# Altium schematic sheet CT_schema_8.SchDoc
size 371 x 336 mm
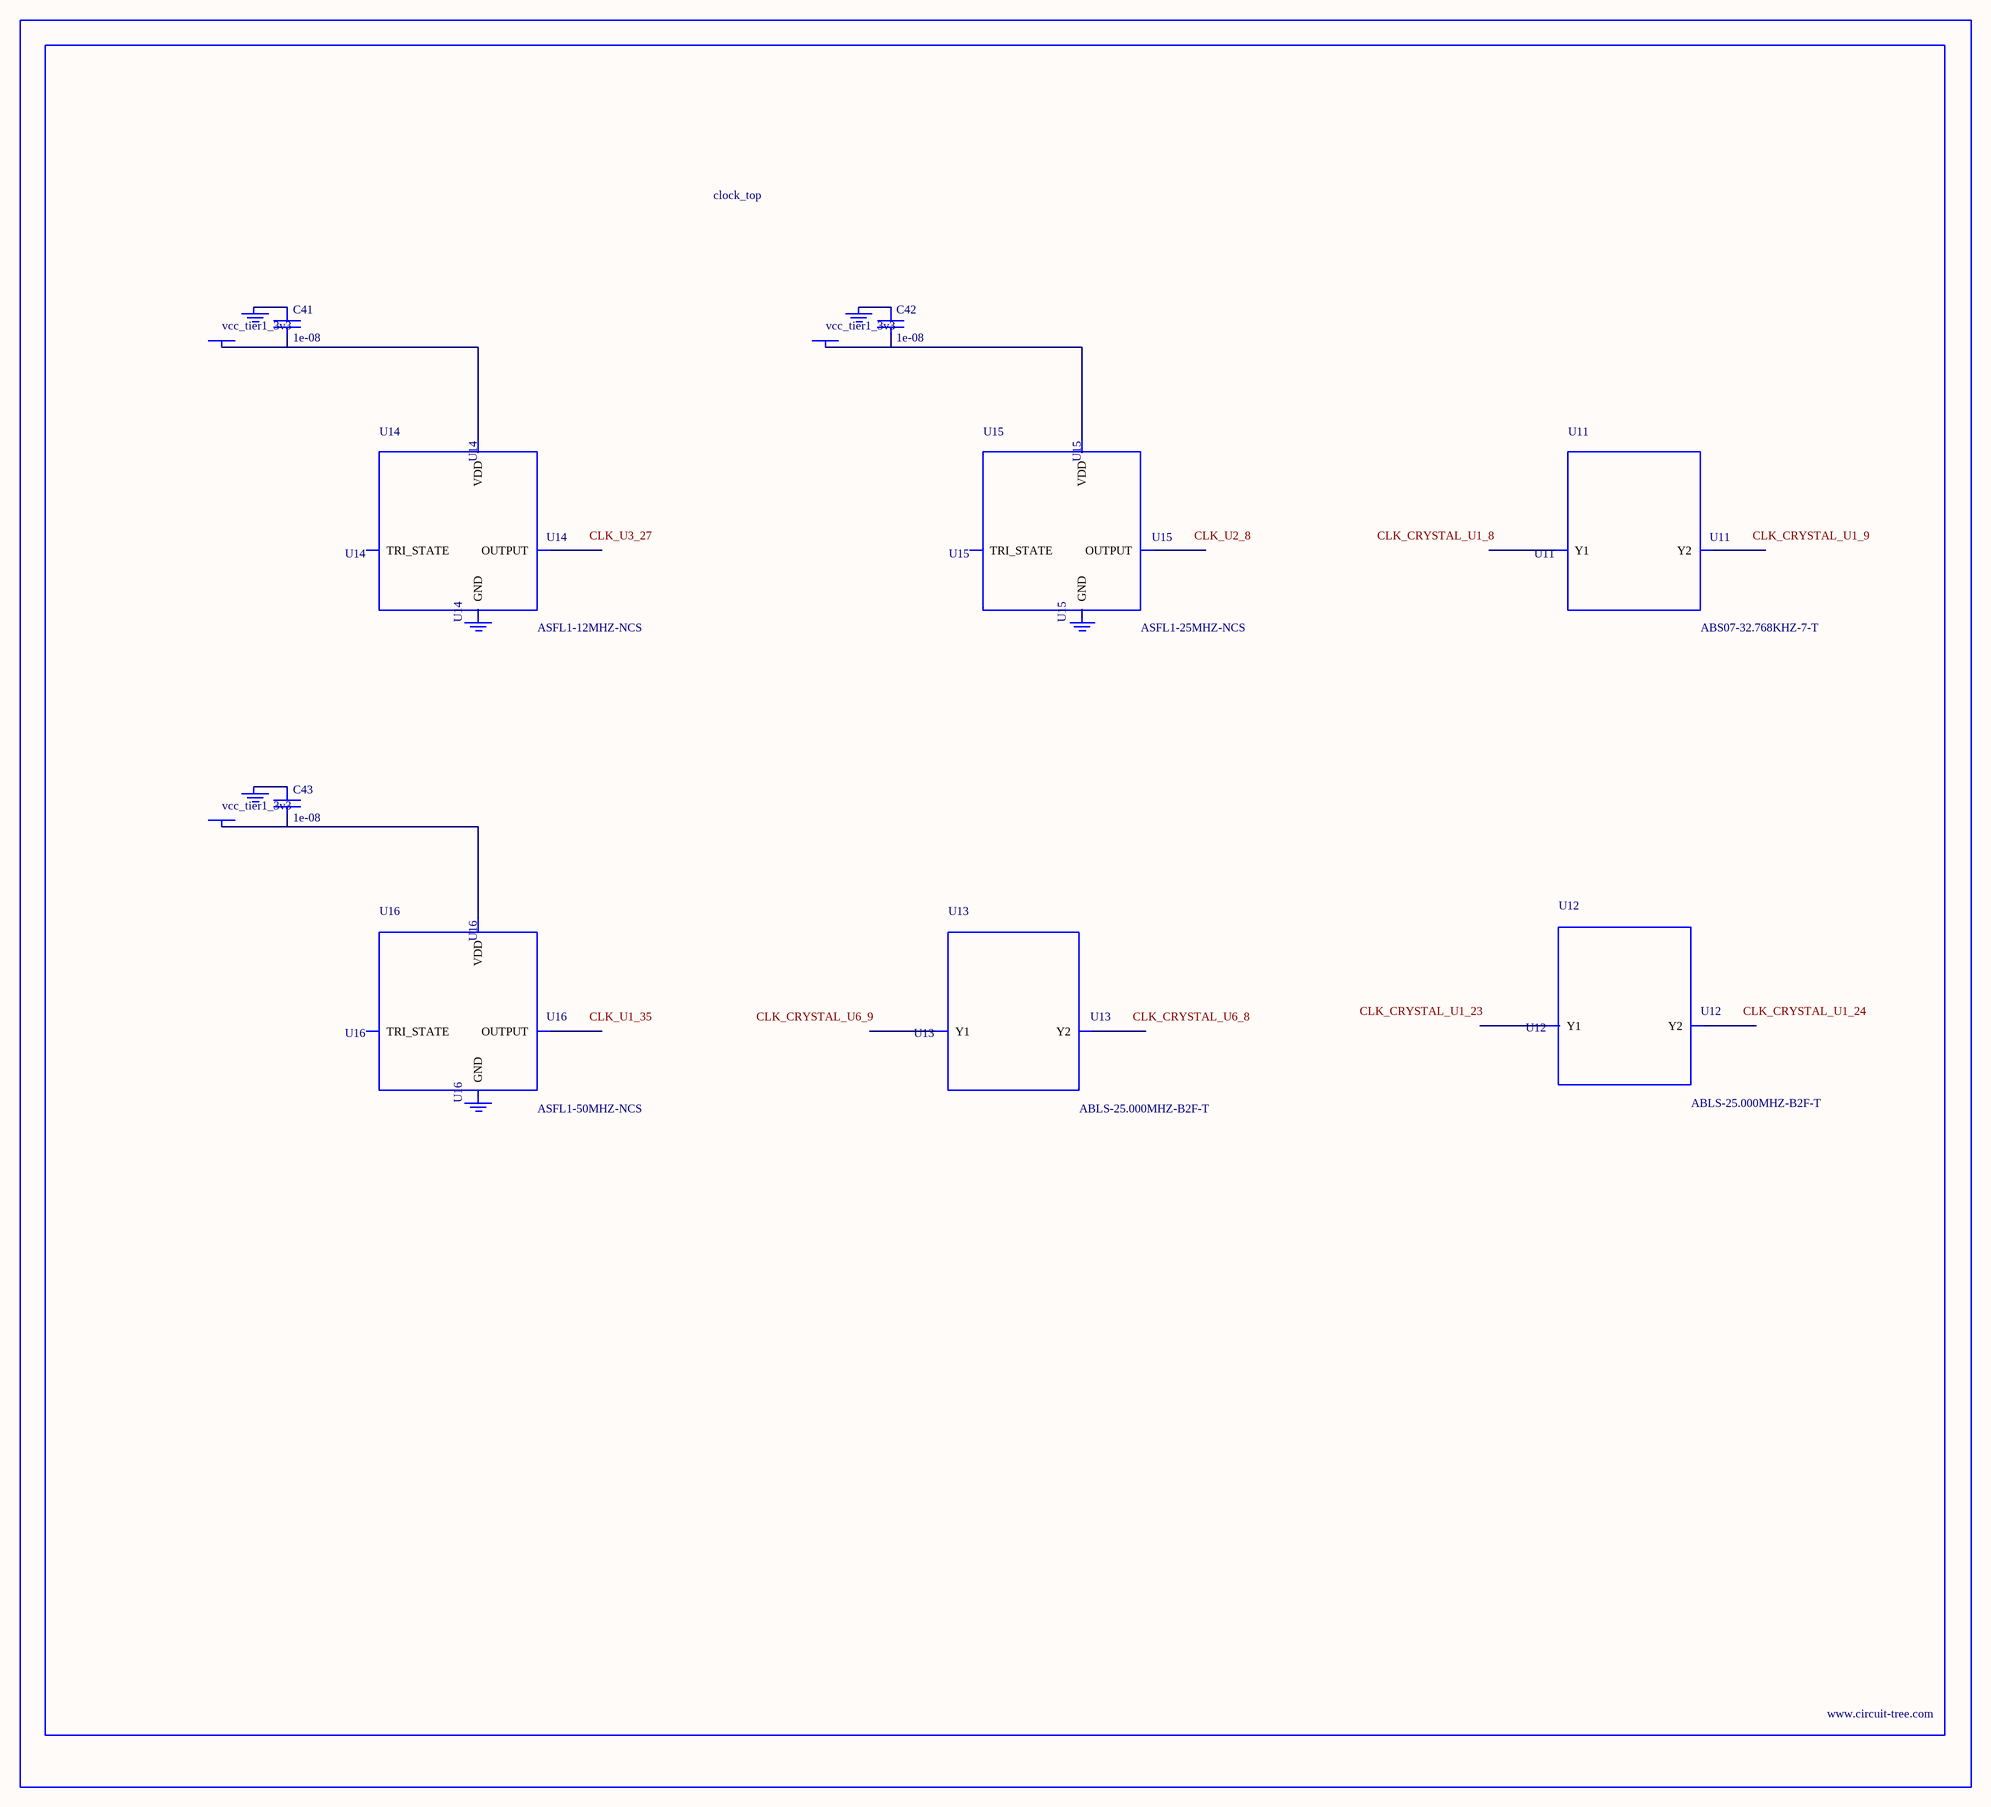
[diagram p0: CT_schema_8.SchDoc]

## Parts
BORDER7  (no value)
C41  1e-08  [C0402]
C42  1e-08  [C0402]
C43  1e-08  [C0402]
GND_INSTANCE_7_0  (no value)
GND_INSTANCE_7_1  (no value)
GND_INSTANCE_7_2  (no value)
GND_INSTANCE_7_3  (no value)
GND_INSTANCE_7_4  (no value)
GND_INSTANCE_7_5  (no value)
POWER_INSTANCE_7_0  vcc_tier1_3v3
POWER_INSTANCE_7_1  vcc_tier1_3v3
POWER_INSTANCE_7_2  vcc_tier1_3v3
U11  ABS07-32.768KHZ-7-T  [ABS07-32.768KHZ-7-T]
U12  ABLS-25.000MHZ-B2F-T  [ABLS-25.000MHZ-B2F-T]
U13  ABLS-25.000MHZ-B2F-T  [ABLS-25.000MHZ-B2F-T]
U14  ASFL1-12MHZ-NCS  [ASFL1]
U15  ASFL1-25MHZ-NCS  [ASFL1]
U16  ASFL1-50MHZ-NCS  [ASFL1]

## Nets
NetC41_1: C41.1 GND_INSTANCE_7_0.0(GND)
NetC41_2: C41.2 POWER_INSTANCE_7_0.0(PWR) U14.4(VDD)
NetC42_1: C42.1 GND_INSTANCE_7_2.0(GND)
NetC42_2: C42.2 POWER_INSTANCE_7_1.0(PWR) U15.4(VDD)
NetC43_1: C43.1 GND_INSTANCE_7_4.0(GND)
NetC43_2: C43.2 POWER_INSTANCE_7_2.0(PWR) U16.4(VDD)

Not connected (* = marked no-connect by the designer): GND_INSTANCE_7_1 0(GND); GND_INSTANCE_7_3 0(GND); GND_INSTANCE_7_5 0(GND); U11 1(Y1) 2(Y2); U12 1(Y1) 2(Y2); U13 1(Y1) 2(Y2); U14 1(TRI_STATE) 2(GND) 3(OUTPUT); U15 1(TRI_STATE) 2(GND) 3(OUTPUT); U16 1(TRI_STATE) 2(GND) 3(OUTPUT)

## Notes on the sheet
- Labels drawn without touching a wire or pin: CLK_CRYSTAL_U1_8, CLK_CRYSTAL_U1_9, CLK_CRYSTAL_U1_23, CLK_CRYSTAL_U1_24, CLK_CRYSTAL_U6_8, CLK_CRYSTAL_U6_9, CLK_U1_35, CLK_U2_8, CLK_U3_27

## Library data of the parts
BORDER7 = BORDER_PAGE7
C41-C43 = C0402C103K3RAC
GND_INSTANCE_7_0-GND_INSTANCE_7_5 = GND
POWER_INSTANCE_7_0-POWER_INSTANCE_7_2 = PWR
